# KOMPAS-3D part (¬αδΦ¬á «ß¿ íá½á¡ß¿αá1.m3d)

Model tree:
1. Эскиз:1
2. Операция выдавливания:1
     Расстояние 1 = 1.5
3. Эскиз:2
4. Операция выдавливания:2
     Расстояние 1 = 2.3
5. Эскиз:7
6. Отверстие:1
7. Эскиз:8
8. Вырезать элемент выдавливания:3
     Расстояние 1 = 2.3
9. Эскиз:9
10. Операция выдавливания:5
     Расстояние 1 = 1
11. Скругление:7
     Радиус = 1
12. Скругление:8
     Радиус = 0.2

Referenced files in C:\Program Files\ASCON\KOMPAS-3D V13 Home\Sys\: holelib.lfr
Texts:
  крышка оси балансира
  Сплав АЛ8  ГОСТ 1583-93
  Отверстие 01
  stalker61
  (вариант 1)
